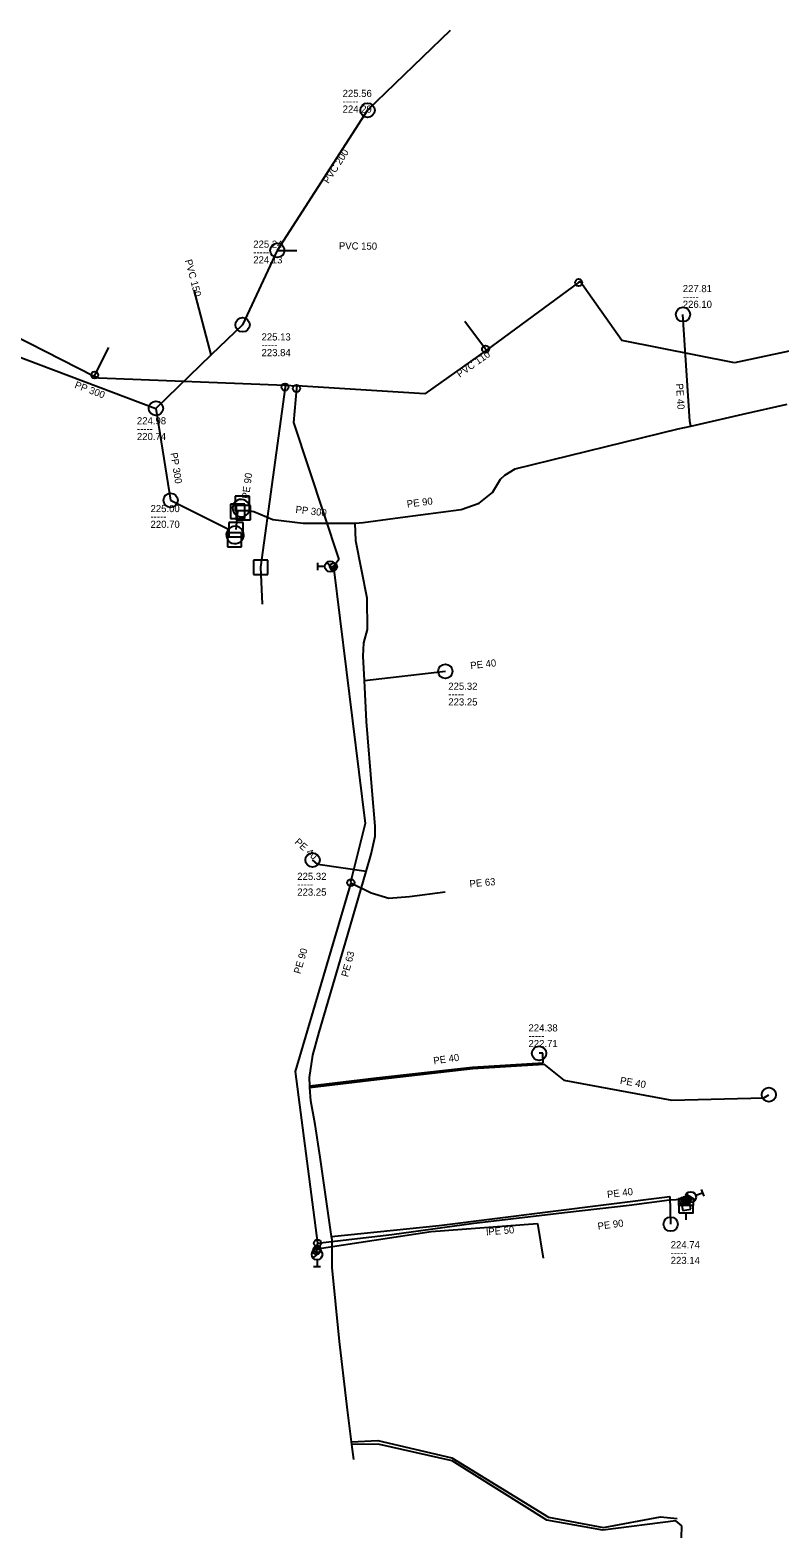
# Model space of a CAD drawing. Extents: x -771212 to -769571, y -1050452 to -1050119.
# Drawn here: x -770920.3 to -770815.2, y -1050452.5 to -1050241.2 of the extents above; entities that cross this region are included whole.
import ezdxf

# ---------------------------------------------------------------- set-up
doc = ezdxf.new("R2010")
doc.units = 0
doc.layers.add('Level 0', color=7, linetype='Continuous')

msp = doc.modelspace()

# ---------------------------------------------------------------- linework, layer by layer
at = {"layer": 'Level 0'}
for p, q in [((-770873.03, -1050252.46), (-770861.42, -1050241.24)), ((-770873.03, -1050252.46), (-770885.68, -1050272.1)), ((-770885.68, -1050272.1), (-770890.55, -1050282.52)), ((-770885.68, -1050272.1), (-770882.93, -1050272.13)), ((-770843.44, -1050276.6), (-770856.36, -1050286.09)), ((-770843.24, -1050276.45), (-770843.44, -1050276.6)), ((-770837.37, -1050284.72), (-770843.24, -1050276.45)), ((-770894.93, -1050286.74), (-770897.33, -1050277.68)), ((-770932.14, -1050279.1), (-770911.37, -1050289.74)), ((-770890.55, -1050282.52), (-770894.93, -1050286.74)), ((-770856.48, -1050285.93), (-770859.37, -1050282.07)), ((-770828.67, -1050283.24), (-770828.81, -1050281.07)), ((-770821.6, -1050287.84), (-770837.37, -1050284.72)), ((-770827.86, -1050296.04), (-770828.67, -1050283.24)), ((-770803.78, -1050284.02), (-770821.6, -1050287.84)), ((-770925.6, -1050285.61), (-770902.7, -1050294.23)), ((-770911.28, -1050289.56), (-770909.32, -1050285.69)), ((-770894.93, -1050286.74), (-770902.7, -1050294.23)), ((-770856.36, -1050286.09), (-770865.02, -1050292.18)), ((-770856.36, -1050286.09), (-770856.48, -1050285.93)), ((-770911.37, -1050289.74), (-770911.28, -1050289.56)), ((-770911.37, -1050289.74), (-770910.71, -1050289.96)), ((-770910.71, -1050289.96), (-770884.6, -1050290.99)), ((-770884.6, -1050291.25), (-770888.02, -1050316.5)), ((-770884.6, -1050290.99), (-770884.6, -1050291.25)), ((-770884.6, -1050290.99), (-770882.93, -1050291.09)), ((-770882.99, -1050291.44), (-770883.43, -1050296.23)), ((-770882.93, -1050291.09), (-770882.99, -1050291.44)), ((-770865.02, -1050292.18), (-770882.93, -1050291.09)), ((-770820.42, -1050295.05), (-770814.21, -1050293.62)), ((-770902.7, -1050294.23), (-770900.64, -1050307.11)), ((-770827.72, -1050296.72), (-770820.42, -1050295.05)), ((-770883.43, -1050296.23), (-770877.05, -1050315.4)), ((-770852.35, -1050302.69), (-770829.48, -1050297.12)), ((-770829.48, -1050297.12), (-770827.72, -1050296.72)), ((-770827.72, -1050296.72), (-770827.86, -1050296.04)), ((-770855.53, -1050306.02), (-770854.38, -1050304.17)), ((-770854.38, -1050304.17), (-770853.77, -1050303.58)), ((-770853.77, -1050303.58), (-770852.35, -1050302.69)), ((-770857.38, -1050307.53), (-770855.53, -1050306.02)), ((-770900.64, -1050307.11), (-770892.51, -1050311.14)), ((-770890.23, -1050307.66), (-770892.23, -1050307.66)), ((-770892.23, -1050307.66), (-770892.23, -1050309.66)), ((-770891.89, -1050307.82), (-770891.95, -1050308.13)), ((-770891.95, -1050308.13), (-770891.93, -1050308.44)), ((-770891.93, -1050308.44), (-770891.84, -1050308.74)), ((-770891.76, -1050307.54), (-770891.89, -1050307.82)), ((-770891.56, -1050307.3), (-770891.76, -1050307.54)), ((-770889.6, -1050306.53), (-770891.6, -1050306.53)), ((-770891.6, -1050306.53), (-770891.6, -1050308.53)), ((-770891.3, -1050307.13), (-770891.56, -1050307.3)), ((-770889.45, -1050307.84), (-770891.45, -1050307.84)), ((-770891.45, -1050307.84), (-770891.45, -1050309.84)), ((-770891.01, -1050307.02), (-770891.3, -1050307.13)), ((-770890.7, -1050306.99), (-770891.01, -1050307.02)), ((-770890.39, -1050307.04), (-770890.7, -1050306.99)), ((-770890.1, -1050307.17), (-770890.39, -1050307.04)), ((-770890.23, -1050309.66), (-770890.23, -1050307.66)), ((-770889.86, -1050307.36), (-770890.1, -1050307.17)), ((-770889.67, -1050307.61), (-770889.86, -1050307.36)), ((-770889.56, -1050307.9), (-770889.67, -1050307.61)), ((-770889.61, -1050308.67), (-770889.53, -1050308.37)), ((-770889.6, -1050308.53), (-770889.6, -1050306.53)), ((-770889.52, -1050308.21), (-770889.56, -1050307.9)), ((-770889.53, -1050308.37), (-770889.52, -1050308.21)), ((-770889.45, -1050309.84), (-770889.45, -1050307.84)), ((-770868.47, -1050309.54), (-770859.9, -1050308.42)), ((-770859.9, -1050308.42), (-770857.38, -1050307.53)), ((-770890.47, -1050310.21), (-770892.47, -1050310.21)), ((-770892.47, -1050310.21), (-770892.47, -1050312.21)), ((-770892.23, -1050309.66), (-770890.23, -1050309.66)), ((-770891.84, -1050308.74), (-770891.67, -1050309)), ((-770891.67, -1050309), (-770891.44, -1050309.21)), ((-770891.6, -1050308.53), (-770889.6, -1050308.53)), ((-770891.47, -1050311.21), (-770891.23, -1050308.66)), ((-770891.45, -1050309.84), (-770889.45, -1050309.84)), ((-770891.44, -1050309.21), (-770891.16, -1050309.35)), ((-770891.16, -1050309.35), (-770890.86, -1050309.42)), ((-770890.86, -1050309.42), (-770890.55, -1050309.41)), ((-770890.55, -1050309.41), (-770890.25, -1050309.32)), ((-770890.47, -1050312.21), (-770890.47, -1050310.21)), ((-770890.25, -1050309.32), (-770889.98, -1050309.16)), ((-770889.98, -1050309.16), (-770889.76, -1050308.94)), ((-770889.76, -1050308.53), (-770888.96, -1050308.68)), ((-770889.76, -1050308.94), (-770889.61, -1050308.67)), ((-770888.96, -1050308.68), (-770886.31, -1050309.82)), ((-770886.31, -1050309.82), (-770882.06, -1050310.32)), ((-770882.06, -1050310.32), (-770874.75, -1050310.3)), ((-770874.75, -1050310.3), (-770873.64, -1050310.22)), ((-770874.65, -1050312.8), (-770874.75, -1050310.3)), ((-770873.64, -1050310.22), (-770868.47, -1050309.54)), ((-770892.77, -1050311.56), (-770892.83, -1050311.87)), ((-770892.83, -1050311.87), (-770892.81, -1050312.18)), ((-770892.81, -1050312.18), (-770892.72, -1050312.48)), ((-770892.63, -1050311.28), (-770892.77, -1050311.56)), ((-770892.72, -1050312.48), (-770892.55, -1050312.74)), ((-770890.68, -1050311.65), (-770892.68, -1050311.65)), ((-770892.68, -1050311.65), (-770892.68, -1050313.65)), ((-770892.42, -1050311.05), (-770892.63, -1050311.28)), ((-770892.55, -1050312.74), (-770892.32, -1050312.96)), ((-770892.47, -1050312.21), (-770890.47, -1050312.21)), ((-770892.17, -1050310.87), (-770892.42, -1050311.05)), ((-770891.87, -1050310.76), (-770892.17, -1050310.87)), ((-770891.56, -1050310.74), (-770891.87, -1050310.76)), ((-770891.25, -1050310.79), (-770891.56, -1050310.74)), ((-770890.97, -1050310.91), (-770891.25, -1050310.79)), ((-770890.72, -1050311.11), (-770890.97, -1050310.91)), ((-770890.86, -1050312.93), (-770890.64, -1050312.71)), ((-770890.54, -1050311.36), (-770890.72, -1050311.11)), ((-770890.68, -1050313.65), (-770890.68, -1050311.65)), ((-770890.64, -1050312.71), (-770890.48, -1050312.44)), ((-770890.42, -1050311.65), (-770890.54, -1050311.36)), ((-770890.48, -1050312.44), (-770890.39, -1050312.14)), ((-770890.38, -1050311.96), (-770890.42, -1050311.65)), ((-770890.39, -1050312.14), (-770890.38, -1050311.96)), ((-770892.68, -1050313.65), (-770890.68, -1050313.65)), ((-770892.32, -1050312.96), (-770892.05, -1050313.1)), ((-770892.05, -1050313.1), (-770891.74, -1050313.18)), ((-770891.74, -1050313.18), (-770891.43, -1050313.17)), ((-770891.43, -1050313.17), (-770891.13, -1050313.09)), ((-770891.13, -1050313.09), (-770890.86, -1050312.93)), ((-770873.1, -1050320.84), (-770874.65, -1050312.8)), ((-770887.02, -1050315.5), (-770889.02, -1050315.5)), ((-770889.02, -1050315.5), (-770889.02, -1050317.5)), ((-770888.02, -1050316.5), (-770887.79, -1050321.68)), ((-770887.02, -1050317.5), (-770887.02, -1050315.5)), ((-770880.01, -1050316.89), (-770880.01, -1050315.89)), ((-770879.01, -1050316.39), (-770880.01, -1050316.39)), ((-770877.8, -1050316.98), (-770878.72, -1050315.8)), ((-770877.8, -1050316.42), (-770878.26, -1050316.39)), ((-770877.05, -1050315.4), (-770877.8, -1050316.42)), ((-770877.8, -1050316.42), (-770873.36, -1050352.39)), ((-770889.02, -1050317.5), (-770887.02, -1050317.5)), ((-770873.04, -1050325.23), (-770873.1, -1050320.84)), ((-770873.53, -1050327.07), (-770873.04, -1050325.23)), ((-770873.65, -1050328.95), (-770873.53, -1050327.07)), ((-770873.47, -1050332.35), (-770873.65, -1050328.95)), ((-770873.47, -1050332.35), (-770862.12, -1050331.07)), ((-770873.17, -1050338.09), (-770873.47, -1050332.35)), ((-770872.39, -1050347.81), (-770873.17, -1050338.09)), ((-770871.95, -1050352.75), (-770872.39, -1050347.81)), ((-770873.36, -1050352.39), (-770875.44, -1050360.6)), ((-770871.94, -1050354.15), (-770871.95, -1050352.75)), ((-770872.54, -1050356.71), (-770871.94, -1050354.15)), ((-770873.24, -1050359.13), (-770872.54, -1050356.71)), ((-770880, -1050358.16), (-770880.74, -1050357.5)), ((-770873.24, -1050359.13), (-770880, -1050358.16)), ((-770876.12, -1050369.07), (-770873.24, -1050359.13)), ((-770875.38, -1050360.69), (-770883.16, -1050387.13)), ((-770875.44, -1050360.6), (-770875.38, -1050360.69)), ((-770875.38, -1050360.69), (-770872.54, -1050362.13)), ((-770872.54, -1050362.13), (-770870.04, -1050362.87)), ((-770870.04, -1050362.87), (-770867.13, -1050362.61)), ((-770867.13, -1050362.61), (-770862.14, -1050361.99)), ((-770879.83, -1050381.61), (-770876.12, -1050369.07)), ((-770880.7, -1050384.86), (-770879.83, -1050381.61)), ((-770881.19, -1050388), (-770880.7, -1050384.86)), ((-770871.76, -1050388.05), (-770858.31, -1050386.52)), ((-770858.31, -1050386.52), (-770848.43, -1050385.94)), ((-770858.29, -1050386.72), (-770848.33, -1050386.13)), ((-770848.46, -1050384.57), (-770848.98, -1050384.59)), ((-770848.43, -1050385.94), (-770848.46, -1050384.57)), ((-770848.33, -1050386.13), (-770845.51, -1050388.37)), ((-770883.16, -1050387.13), (-770880.04, -1050411.18)), ((-770881.12, -1050389.16), (-770881.19, -1050388)), ((-770881.12, -1050389.16), (-770871.76, -1050388.05)), ((-770881.11, -1050389.36), (-770871.74, -1050388.25)), ((-770871.74, -1050388.25), (-770858.29, -1050386.72)), ((-770845.51, -1050388.37), (-770830.37, -1050391.18)), ((-770881.11, -1050389.36), (-770881.12, -1050389.16)), ((-770880.99, -1050391.24), (-770881.11, -1050389.36)), ((-770830.37, -1050391.18), (-770817.46, -1050390.85)), ((-770817.46, -1050390.85), (-770816.78, -1050390.39)), ((-770880.38, -1050394.58), (-770880.99, -1050391.24)), ((-770879.68, -1050399.16), (-770880.38, -1050394.58)), ((-770878.07, -1050410.27), (-770879.68, -1050399.16)), ((-770847.74, -1050406.8), (-770830.67, -1050404.65)), ((-770836.34, -1050405.86), (-770830.68, -1050405.1)), ((-770830.68, -1050405.1), (-770828.82, -1050405.03)), ((-770830.67, -1050404.65), (-770830.54, -1050408.53)), ((-770827.93, -1050405.23), (-770829.05, -1050405.45)), ((-770829.05, -1050405.45), (-770828.82, -1050406.63)), ((-770828.82, -1050405.03), (-770828.52, -1050404.99)), ((-770828.82, -1050405.03), (-770828.76, -1050405.26)), ((-770828.76, -1050405.26), (-770828.73, -1050405.96)), ((-770828.52, -1050404.99), (-770828.26, -1050404.93)), ((-770828.52, -1050404.99), (-770828.48, -1050405.17)), ((-770828.48, -1050405.17), (-770828.44, -1050405.94)), ((-770828.37, -1050404.35), (-770827.09, -1050405.14)), ((-770828.26, -1050404.93), (-770827.73, -1050404.74)), ((-770828.26, -1050404.93), (-770828.23, -1050405.14)), ((-770828.23, -1050405.14), (-770828.12, -1050405.92)), ((-770827.7, -1050406.41), (-770827.93, -1050405.23)), ((-770827.03, -1050404.48), (-770826.09, -1050404.14)), ((-770826.26, -1050403.67), (-770825.91, -1050404.61)), ((-770863.01, -1050408.7), (-770847.74, -1050406.8)), ((-770858.11, -1050408.4), (-770844.98, -1050406.84)), ((-770844.98, -1050406.84), (-770836.34, -1050405.86)), ((-770828.82, -1050406.63), (-770827.7, -1050406.41)), ((-770828.38, -1050407.93), (-770828.38, -1050406.93)), ((-770880.07, -1050412), (-770864.12, -1050409.55)), ((-770878.07, -1050410.27), (-770863.01, -1050408.7)), ((-770869.63, -1050409.98), (-770858.11, -1050408.4)), ((-770864.12, -1050409.55), (-770849.22, -1050408.42)), ((-770849.22, -1050408.42), (-770848.4, -1050413.28)), ((-770880.04, -1050411.18), (-770880.22, -1050411.99)), ((-770880.22, -1050411.99), (-770880.07, -1050412)), ((-770880.22, -1050411.99), (-770880.19, -1050412.27)), ((-770880.04, -1050411.18), (-770869.63, -1050409.98)), ((-770878, -1050410.74), (-770878.07, -1050410.27)), ((-770877.99, -1050414.61), (-770878, -1050410.74)), ((-770879.52, -1050412.31), (-770880.7, -1050413.23)), ((-770880.19, -1050412.27), (-770880.11, -1050412.77)), ((-770880.11, -1050413.52), (-770880.11, -1050414.52)), ((-770879.61, -1050414.52), (-770880.61, -1050414.52)), ((-770876.95, -1050424.99), (-770877.99, -1050414.61)), ((-770875.86, -1050434.55), (-770876.95, -1050424.99)), ((-770875.28, -1050439.02), (-770875.86, -1050434.55)), ((-770875.28, -1050439.02), (-770871.61, -1050438.83)), ((-770875.23, -1050439.39), (-770875.28, -1050439.02)), ((-770871.55, -1050439.35), (-770875.23, -1050439.39)), ((-770874.95, -1050441.52), (-770875.23, -1050439.39)), ((-770871.61, -1050438.83), (-770861.21, -1050441.26)), ((-770861.17, -1050441.68), (-770871.55, -1050439.35)), ((-770861.21, -1050441.26), (-770847.68, -1050449.57)), ((-770847.89, -1050449.99), (-770861.17, -1050441.68)), ((-770840.04, -1050451.42), (-770847.89, -1050449.99)), ((-770847.68, -1050449.57), (-770839.95, -1050451.04)), ((-770839.95, -1050451.04), (-770831.94, -1050449.54)), ((-770831.94, -1050449.54), (-770829.63, -1050449.78)), ((-770829.83, -1050450.09), (-770840.04, -1050451.42)), ((-770828.99, -1050450.8), (-770829.83, -1050450.09)), ((-770829.01, -1050452.48), (-770828.99, -1050450.8))]:
    msp.add_line(p, q, dxfattribs=at)
msp.add_lwpolyline([(-770829.38, -1050405.93), (-770829.38, -1050404.93), (-770827.38, -1050404.93), (-770827.38, -1050405.93)], dxfattribs=at)
msp.add_lwpolyline([(-770829.38, -1050406.93), (-770827.38, -1050406.93), (-770827.38, -1050405.93), (-770829.38, -1050405.93)], close=True, dxfattribs=at)
for centre, radius in [((-770873.03, -1050252.46), 1), ((-770885.68, -1050272.1), 1), ((-770843.44, -1050276.6), 0.5), ((-770828.81, -1050281.07), 1), ((-770890.55, -1050282.52), 1), ((-770856.48, -1050285.93), 0.5), ((-770911.28, -1050289.56), 0.5), ((-770884.6, -1050291.25), 0.5), ((-770882.99, -1050291.44), 0.5), ((-770902.7, -1050294.23), 1), ((-770900.64, -1050307.11), 1), ((-770878.26, -1050316.39), 0.75), ((-770877.8, -1050316.42), 0.5), ((-770862.12, -1050331.07), 1), ((-770880.74, -1050357.5), 1), ((-770875.38, -1050360.69), 0.5), ((-770848.98, -1050384.59), 1), ((-770816.78, -1050390.39), 1), ((-770828.76, -1050405.26), 0.5), ((-770828.48, -1050405.17), 0.5), ((-770828.23, -1050405.14), 0.5), ((-770827.73, -1050404.74), 0.75), ((-770830.54, -1050408.53), 1), ((-770880.11, -1050412.77), 0.75), ((-770880.19, -1050412.27), 0.5), ((-770880.07, -1050412), 0.5), ((-770880.04, -1050411.18), 0.5)]:
    msp.add_circle(centre, radius, dxfattribs=at)

# ---------------------------------------------------------------- texts
for s, p in [('-----', (-770876.52, -1050251.7)), ('225.56', (-770876.52, -1050250.6)), ('224.29', (-770876.52, -1050252.8)), ('-----', (-770889.05, -1050272.82)), ('225.24', (-770889.05, -1050271.72)), ('224.13', (-770889.05, -1050273.92)), ('-----', (-770828.84, -1050279.05)), ('227.81', (-770828.84, -1050277.95)), ('226.10', (-770828.84, -1050280.15)), ('225.13', (-770887.89, -1050284.72)), ('-----', (-770887.89, -1050285.82)), ('223.84', (-770887.89, -1050286.92)), ('224.98', (-770905.36, -1050296.47)), ('-----', (-770905.36, -1050297.57)), ('220.74', (-770905.36, -1050298.67)), ('225.00', (-770903.45, -1050308.77)), ('-----', (-770903.45, -1050309.87)), ('220.70', (-770903.45, -1050310.97)), ('225.32', (-770861.71, -1050333.66)), ('-----', (-770861.71, -1050334.76)), ('223.25', (-770861.71, -1050335.86)), ('-----', (-770882.88, -1050361.4)), ('225.32', (-770882.88, -1050360.3)), ('223.25', (-770882.88, -1050362.5)), ('-----', (-770850.47, -1050382.63)), ('224.38', (-770850.47, -1050381.53)), ('222.71', (-770850.47, -1050383.73)), ('224.74', (-770830.53, -1050411.91)), ('-----', (-770830.53, -1050413.01)), ('223.14', (-770830.53, -1050414.11))]:
    msp.add_text(s, height=1, dxfattribs=at).set_placement(p)
for s, rotation, p in [('PVC 200', 57.215, (-770878.51, -1050262.82)), ('PVC 150', 359.375, (-770877.05, -1050271.95)), ('PVC 150', 284.837, (-770898.64, -1050273.5)), ('PVC 110', 35.116, (-770860.11, -1050289.95)), ('PP 300', 339.373, (-770914.18, -1050291.33)), ('PE 40', 273.621, (-770829.8, -1050290.78)), ('PP 300', 279.087, (-770900.68, -1050300.51)), ('PE 90', 82.286, (-770889.68, -1050306.95)), ('PP 300', 353.29, (-770883.17, -1050308.86)), ('PE 90', 7.259, (-770867.46, -1050308.14)), ('PE 40', 6.434, (-770858.57, -1050330.77)), ('PE 40', 318.27, (-770883.33, -1050355.11)), ('PE 63', 5.106, (-770858.69, -1050361.34)), ('PE 90', 73.775, (-770882.45, -1050373.54)), ('PE 63', 75.014, (-770875.78, -1050373.97)), ('PE 40', 7.957, (-770863.73, -1050386.14)), ('PE 40', 350.189, (-770837.69, -1050388.86)), ('PE 40', 7.179, (-770839.39, -1050404.88)), ('lPE 50', 4.337, (-770856.36, -1050410.1)), ('PE 90', 7.648, (-770840.71, -1050409.33))]:
    msp.add_text(s, height=1, rotation=rotation, dxfattribs=at).set_placement(p)

doc.saveas('drawing.dxf')
